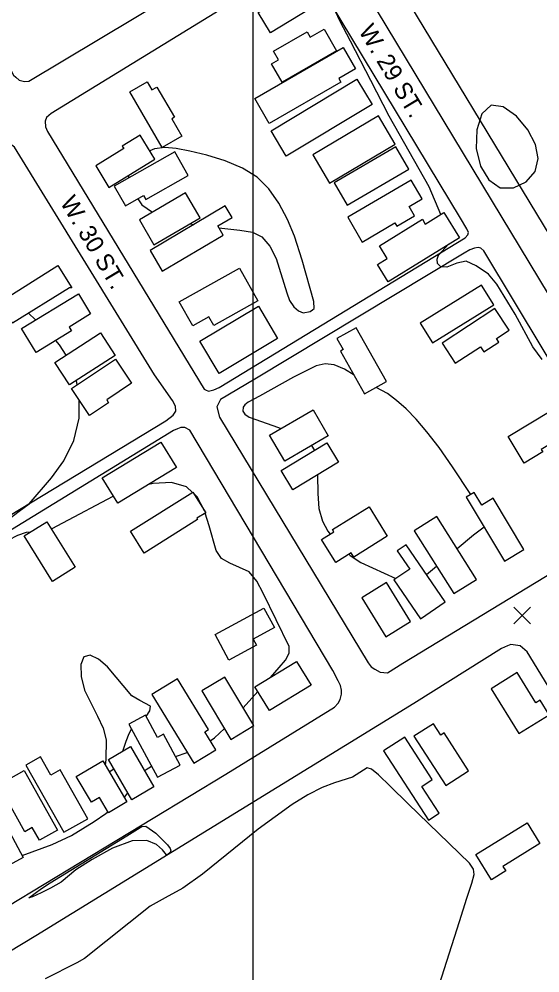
# Model space of a CAD drawing. Extents: x 79600 to 91800, y 75600 to 84400.
# Drawn here: x 82798 to 83248, y 82011 to 82835 of the extents above; entities that cross this region are included whole.
import ezdxf

# ---------------------------------------------------------------- set-up
doc = ezdxf.new("R2010")
doc.units = 0
for name, color, linetype in [('084-085$0$BLDG', 7, 'Continuous'), ('084-085$0$GRID', 7, 'Continuous'), ('084-085$0$INDEX', 7, 'Continuous'), ('084-085$0$INTER', 7, 'Continuous'), ('084-085$0$RECREATION', 7, 'Continuous'), ('084-085$0$ROAD', 7, 'Continuous'), ('084-085$0$ROAD-NAME', 7, 'Continuous'), ('084-085$0$SPOTMARK', 7, 'Continuous'), ('084-085$0$SPOTS', 7, 'Continuous')]:
    doc.layers.add(name, color=color, linetype=linetype)

# ---------------------------------------------------------------- blocks, each defined once
blk = doc.blocks.new('084-085$0$SPOTX')
at = {"layer": '084-085$0$SPOTMARK'}
for p, q in [((-0.37, 0.358), (0.351, -0.358)), ((-0.012, 0), (-0.37, -0.358)), ((-0.012, 0), (0.347, 0.358))]:
    blk.add_line(p, q, dxfattribs=at)

msp = doc.modelspace()

# ---------------------------------------------------------------- linework, layer by layer
at = {"layer": '084-085$0$BLDG'}
for points in [[(83015.3, 82822.83), (83004.54, 82840.42), (83038.07, 82860.94), (83048.83, 82843.35)], [(83016.15, 82796.11), (83022.2, 82799.6), (83017.83, 82807.18), (83046.8, 82823.89), (83049.6, 82819.04), (83061.6, 82825.96), (83072.31, 82807.38), (83025.28, 82780.27)], [(83088.61, 82791.88), (83074.18, 82783.56), (83075.99, 82780.41), (83014.12, 82744.74), (83001.74, 82766.21), (83078.06, 82810.2)], [(82908.66, 82780.58), (82912.7, 82773.56), (82917.14, 82776.11), (82932.15, 82750.04), (82929.94, 82748.76), (82938.65, 82733.63), (82921.54, 82723.78), (82893.77, 82772.01)], [(83103.08, 82760.93), (83028.91, 82716.48), (83015.82, 82738.32), (83089.99, 82782.77)], [(83051.71, 82717.62), (83066.14, 82693.1), (83123.12, 82726.63), (83108.69, 82751.15)], [(82915.32, 82713.82), (82902.59, 82734.5), (82887.19, 82725.03), (82888.52, 82722.88), (82864.18, 82707.9), (82875.58, 82689.37)], [(83081.55, 82673.99), (83134.77, 82705.04), (83123.5, 82724.36), (83070.28, 82693.3)], [(82905.49, 82682.34), (82907.41, 82678.95), (82944.17, 82699.8), (82932.63, 82720.17), (82880.24, 82690.46), (82889.87, 82673.48)], [(83094.58, 82642.23), (83122.83, 82658.74), (83124.51, 82655.87), (83139.74, 82664.78), (83135.04, 82672.83), (83146.46, 82679.5), (83136.96, 82695.76), (83082.05, 82663.65)], [(82941.93, 82684.68), (82901.91, 82661.33), (82914.53, 82639.7), (82954.55, 82663.06)], [(82969.61, 82656.1), (82982.05, 82663.44), (82976.21, 82673.35), (82911.11, 82634.94), (82921.7, 82616.99), (82974.35, 82648.06)], [(83107.86, 82622.75), (83116.21, 82627.89), (83109.32, 82639.08), (83146.48, 82661.95), (83149.03, 82657.8), (83165.13, 82667.71), (83178.59, 82645.85), (83116.98, 82607.92)], [(82843.49, 82602.81), (82841.44, 82602.8), (82792.23, 82572.07), (82780.89, 82590.24), (82831.58, 82621.89)], [(82966.34, 82570.01), (82962.01, 82577.68), (82948.12, 82569.82), (82936.45, 82590.44), (82988.34, 82619.79), (83004.34, 82591.51)], [(83155.38, 82555.04), (83208.17, 82587.86), (83197.48, 82605.04), (83144.7, 82572.22)], [(82859.81, 82580.08), (82841.26, 82568.79), (82843.28, 82565.46), (82812.72, 82546.86), (82800.07, 82567.65), (82849.18, 82597.54)], [(83004.74, 82586.78), (83021.36, 82558.92), (82970.83, 82528.78), (82954.21, 82556.64)], [(83174.95, 82537.6), (83196.66, 82551.82), (83199.55, 82547.41), (83212.47, 82555.88), (83210.47, 82558.94), (83221.47, 82566.15), (83209.25, 82584.79), (83163.62, 82554.89)], [(83072.61, 82558.81), (83078.03, 82549.3), (83075.63, 82547.93), (83096.61, 82511.05), (83115.6, 82521.85), (83089.21, 82568.25)], [(82880.91, 82544.2), (82841.56, 82518.75), (82828.92, 82538.28), (82868.28, 82563.73)], [(82873.77, 82505.89), (82875.38, 82503.47), (82858.74, 82492.35), (82843.21, 82515.6), (82881.29, 82541.04), (82895.2, 82520.21)], [(83014.52, 82475.42), (83052.09, 82497.23), (83065.1, 82474.82), (83027.53, 82453.02)], [(83249.29, 82463.13), (83250.55, 82461.08), (83234.61, 82451.33), (83220.66, 82474.13), (83258.29, 82497.15), (83270.99, 82476.4)], [(82869.87, 82438.45), (82920.57, 82469.31), (82933.87, 82447.47), (82883.17, 82416.61)], [(83024.47, 82444.91), (83063.99, 82468.78), (83074.14, 82451.97), (83034.62, 82428.1)], [(82951.63, 82403.66), (82952.3, 82402.59), (82906.15, 82373.63), (82894.31, 82392.5), (82948.1, 82426.25), (82959.27, 82408.45)], [(83197.9, 82414.94), (83191.32, 82425.93), (83184.46, 82421.82), (83217.53, 82366.64), (83234.29, 82376.69), (83207.8, 82420.87)], [(83085, 82373.66), (83071.79, 82365.44), (83059.42, 82385.31), (83070.12, 82391.97), (83068.97, 82393.81), (83100.41, 82413.38), (83116.11, 82388.15), (83087.19, 82370.14)], [(82826.75, 82349.1), (82802.39, 82388.33), (82821.98, 82400.5), (82846.35, 82361.27)], [(83139.44, 82392.93), (83173.76, 82338.53), (83193.34, 82350.88), (83159.02, 82405.28)], [(83124.82, 82375.56), (83135.61, 82359.79), (83121.9, 82350.41), (83144.89, 82316.8), (83166.23, 82331.4), (83132.45, 82380.78)], [(83094.05, 82334.82), (83114.8, 82301.35), (83136.17, 82314.59), (83115.43, 82348.07)], [(83018.67, 82309.21), (83000.37, 82299.3), (83003.25, 82294), (82979.33, 82281.04), (82967.3, 82303.25), (83009.51, 82326.11)], [(83050.36, 82259.45), (83014.32, 82237.58), (83001.83, 82258.16), (83037.86, 82280.03)], [(83256.03, 82233.98), (83248.35, 82246.4), (83244.7, 82244.15), (83228.52, 82270.31), (83206.02, 82256.4), (83229.88, 82217.81)], [(82967.98, 82203.58), (82958.49, 82219.08), (82961.78, 82221.09), (82934.92, 82265), (82912.67, 82251.38), (82949.01, 82191.98)], [(83000.85, 82224.59), (82975.73, 82266.46), (82955.9, 82254.57), (82981.01, 82212.69)], [(82922.73, 82217.22), (82917.5, 82214.39), (82907.17, 82233.46), (82892.9, 82225.73), (82917.72, 82179.9), (82937.22, 82190.46)], [(83186.45, 82185.64), (83165.44, 82218.28), (83162.39, 82216.32), (83156.01, 82226.22), (83139.27, 82215.44), (83166.67, 82172.9)], [(83161.03, 82148.85), (83146.02, 82172.01), (83155.1, 82177.89), (83131.26, 82214.66), (83112.9, 82202.76), (83151.75, 82142.83)], [(82895.37, 82160.58), (82875.13, 82195.34), (82894.31, 82206.5), (82914.55, 82171.75)], [(82825.44, 82181.72), (82816.42, 82197.65), (82803.87, 82190.54), (82836.77, 82132.41), (82857.32, 82144.04), (82833.43, 82186.24)], [(82875.11, 82149.26), (82867.4, 82162.44), (82860.46, 82158.38), (82847.41, 82180.7), (82870.31, 82194.09), (82891.07, 82158.6)], [(82815.55, 82125.55), (82809.38, 82136.53), (82803, 82132.94), (82780.28, 82173.33), (82802.3, 82185.72), (82831.19, 82134.35)], [(82789.44, 82104.17), (82790.73, 82104.17), (82790.23, 82103.9), (82787.68, 82108.59), (82780.37, 82104.61), (82759.19, 82143.54), (82778.05, 82153.8), (82801.48, 82110.72)], [(83216.13, 82102.96), (83218.6, 82099), (83206.35, 82091.38), (83192.77, 82113.21), (83236.96, 82140.7), (83248.08, 82122.83)]]:
    msp.add_lwpolyline(points, close=True, dxfattribs=at)
at = {"layer": '084-085$0$GRID'}
msp.add_line((83000, 84000), (83000, 80000), dxfattribs=at)
at = {"layer": '084-085$0$INDEX'}
for points in [[(83162.6, 82666.15), (83152.51, 82689.84), (83117.84, 82750.87), (83101.85, 82781.84), (83084.37, 82815.78), (83075.04, 82833.28), (83067.83, 82848.78)], [(83250.06, 82540.81), (83242, 82551.82), (83226.63, 82579.9), (83210.86, 82605.93), (83203.57, 82614.58), (83193.04, 82621.81), (83184.49, 82625.76), (83176.27, 82623.95), (83167.71, 82620.66), (83162.45, 82620.83), (83159.49, 82623.62), (83159.16, 82627.4), (83160.31, 82630.86), (83169.03, 82640.39)]]:
    msp.add_lwpolyline(points, dxfattribs=at)
for points in [[(83237.75, 82739.25), (83227.82, 82751.02), (83216.47, 82759.14), (83205.9, 82760.43), (83198.04, 82752.88), (83193.64, 82739.12), (83193.13, 82722.9), (83196.77, 82707.72), (83203.93, 82695.81), (83213.8, 82689.11), (83225.27, 82688.94), (83236.12, 82694.2), (83243.87, 82703.18), (83246.55, 82714.3), (83244.3, 82726.6)], [(82824.81, 82088.73), (82891.07, 82129.32), (82902.57, 82136.44), (82904.07, 82137.43), (82907.5, 82137.61), (82916.29, 82131.61), (82926.25, 82121.63), (82928.5, 82118.41), (82929.02, 82116.54), (82928.14, 82114.73), (82926.72, 82113.5), (82925.3, 82112.87), (82921.89, 82117.28), (82916.86, 82121.8), (82908.34, 82125.45), (82895.59, 82125.06), (82878.7, 82118.66), (82861.09, 82108.98), (82847.03, 82099.97), (82834.47, 82089.46), (82825.2, 82084.18), (82817.03, 82080.11), (82809.49, 82076.68), (82806.26, 82075.83), (82817.22, 82083.86)]]:
    msp.add_lwpolyline(points, close=True, dxfattribs=at)
at = {"layer": '084-085$0$INTER'}
for p, q in [((82892.18, 82699.58), (82892.9, 82697.64)), ((82945.72, 82657.91), (82948.94, 82657.26)), ((82812.15, 82575), (82806.08, 82580.72)), ((82848.3, 82519), (82847.65, 82522.69)), ((83050.65, 82466.44), (83053.23, 82462.28)), ((83150.1, 82354.98), (83158.76, 82362.31)), ((82991.65, 82239.92), (83004.3, 82254.09)), ((82933.25, 82197.79), (82943.34, 82201.25)), ((82875.85, 82184.63), (82879.79, 82187.35))]:
    msp.add_line(p, q, dxfattribs=at)
for points in [[(83051.57, 82583.61), (83052.97, 82584.84), (83052.76, 82590.92), (83042.54, 82626.61), (83035.88, 82647.28), (83029.89, 82661.66), (83022.51, 82675.9), (83013.93, 82688.12), (83003.68, 82698.12), (82991.14, 82706.15), (82976.14, 82712.45), (82960.29, 82717.24), (82945.63, 82720.73), (82933.68, 82723.04), (82923.86, 82723.83), (82915.01, 82722.65), (82910.86, 82721.05)], [(82900.47, 82679.49), (82904.01, 82674.3), (82913.17, 82667.9)], [(82970.57, 82654.48), (82988.79, 82652.53), (82999.61, 82650.89), (83007.78, 82646.72), (83014.58, 82638.62), (83020.15, 82627.96), (83029.28, 82598.43), (83031.8, 82591.61), (83035.34, 82586.4), (83039.48, 82582.89), (83043.52, 82581.15), (83049.55, 82582.23), (83051.57, 82583.61)], [(82838.78, 82544.65), (82832.89, 82553.58), (82829.66, 82557.17)], [(83087.45, 82527.14), (83079.09, 82532.29), (83070.39, 82536.22), (83062.51, 82537.16), (83054.71, 82535.27), (83035.16, 82525.4), (83005.67, 82509.23), (82995.88, 82503.81), (82993.2, 82501.65), (82991.68, 82499.63), (82991.47, 82496.07), (82993.21, 82493.58), (82996.76, 82491.01), (83017.15, 82483.7), (83024.48, 82481.2)], [(83188.4, 82424.17), (83172.68, 82448.01), (83160.89, 82464.65), (83150.46, 82478.36), (83141.24, 82489.25), (83132.61, 82498.07), (83124.19, 82505.44), (83116.41, 82511.27), (83106.51, 82516.69)], [(82750.96, 82362.41), (82748.65, 82361.81), (82741.75, 82361.86), (82743.31, 82366.31), (82763.72, 82383.73), (82797.97, 82409.65), (82806.57, 82416.18), (82825.99, 82438.65), (82836.56, 82453.38), (82845.36, 82470.94), (82849.81, 82490.05), (82850.02, 82505.41)], [(82947.75, 82426.03), (82942.67, 82430.78), (82929.68, 82434.47), (82913.91, 82433.61), (82909.08, 82432.38)], [(83055.86, 82440.93), (83056.05, 82425.14), (83057.07, 82411.94), (83060.12, 82401.13), (83064.86, 82392.38), (83066.88, 82389.95)], [(82958.22, 82410.12), (82952, 82422.06), (82948.93, 82424.93)], [(82879.51, 82422.62), (82878.98, 82422.41), (82835.45, 82399.47), (82826.23, 82394.39), (82825.87, 82394.24)], [(83015.16, 82266.25), (83022.85, 82274.86), (83028.3, 82281.05), (83031.5, 82287.07), (83031.47, 82292.88), (83008.89, 82338.99), (83003.52, 82349.23), (82996.8, 82357.27), (82980.06, 82364.86), (82972.93, 82368.79), (82968.29, 82375.67), (82962.32, 82397.14), (82958.84, 82408.18)], [(83176.61, 82377.41), (83190.6, 82389.25), (83199.87, 82396.11)], [(82807.87, 82391.74), (82803.95, 82391.49), (82796.56, 82388.86), (82788.82, 82384.65), (82779.43, 82376.23), (82776.51, 82372.69), (82770.67, 82368.93), (82768.33, 82368.02)], [(83083.12, 82372.49), (83084.11, 82371.62), (83093.45, 82365.5), (83123.47, 82351.49)], [(82907.77, 82232.34), (82910.9, 82237.19), (82911.56, 82241.3), (82902.41, 82246.12), (82895.3, 82250.22), (82874.34, 82275.29), (82866.67, 82282.08), (82859.48, 82285.44), (82854.03, 82284.09), (82851.34, 82277.35), (82851.52, 82266.91), (82854.45, 82255.05), (82865.76, 82232.81), (82870.7, 82222.41), (82873.13, 82212.33), (82872.98, 82195.18), (82872.44, 82190.46)], [(82887.51, 82202.54), (82890.48, 82211.08), (82893.13, 82217.64), (82895.23, 82221.43)], [(82963.13, 82211.49), (82966.78, 82214.01), (82975.39, 82222.06)], [(83156.74, 81986.87), (83178.47, 82055.42), (83184.98, 82075.62), (83189.36, 82088.51), (83191.29, 82095.85), (83190.67, 82100.63), (83187.22, 82105.64), (83134.23, 82157), (83118.7, 82172.2), (83108.5, 82182.1), (83102.55, 82187), (83098.77, 82188.05), (83086.1, 82180.16), (83070.43, 82175.04), (83059.87, 82171.07), (83047.59, 82164.78), (83033.97, 82156.37), (83004.68, 82135.21), (82956.6, 82096.15), (82939.44, 82084.11), (82924.33, 82075.87), (82911.2, 82068.66), (82854.51, 82023.51), (82847.84, 82019.79), (82820.6, 82005.93)], [(82906.51, 82185.54), (82907.87, 82186.74), (82912.51, 82189.52)], [(82888.82, 82162.45), (82889.29, 82162.91), (82891.87, 82166.6)], [(82800.51, 82112.49), (82826.5, 82121.77), (82843.25, 82129.63), (82862.87, 82141.86), (82872.79, 82148.72), (82874.6, 82150.13)]]:
    msp.add_lwpolyline(points, dxfattribs=at)
at = {"layer": '084-085$0$RECREATION'}
msp.add_lwpolyline([(83263.53, 82636.72), (83111.76, 82887.32), (83287.39, 82994.15), (83433.35, 82754.08), (83376.35, 82718.43)], dxfattribs=at)
at = {"layer": '084-085$0$ROAD'}
for points in [[(82508.5, 83257.27), (82791, 82789.98), (82793.2, 82786.42), (82795.08, 82784.57), (82797.89, 82782.1), (82802.72, 82780.89), (82806.45, 82781.06), (83019.27, 82908.66)], [(83090.72, 82869.46), (83354.53, 82432.68), (83357.19, 82429.59), (83364.83, 82425.91), (83369.81, 82426.09), (83373.37, 82427.52), (83581.54, 82552.75), (83584.32, 82555.56), (83585.86, 82558.53), (83586.13, 82564.44), (83584.85, 82569.87), (83575.58, 82585.98), (83306.91, 83030.5)], [(82793.9, 82724.24), (82790.47, 82726.7), (82787.82, 82727.46), (82780.21, 82725.55), (82776.49, 82723.66), (82595.27, 82614.3), (82592.02, 82611.95), (82591.26, 82610.24), (82590.96, 82608.37), (82591.14, 82604.95), (82592.87, 82601.69), (82729.53, 82380.38), (82731.25, 82378.22), (82733.44, 82376.99), (82736.86, 82376.7), (82741.52, 82377.04), (82750.51, 82382.53), (82924.91, 82487.81)], [(82924.91, 82487.81), (82931.1, 82492.66), (82933.41, 82496.26), (82933.22, 82500.45), (82930.55, 82505.26), (82915.02, 82527.39), (82793.9, 82724.24)], [(82725.05, 82030.69), (82976.59, 82182.62), (83070.44, 82240.58), (83073.84, 82243.87), (83075.38, 82247.15), (83076.59, 82251.66), (83076.57, 82255.24), (83075.76, 82259.28), (83073.87, 82263.31), (83069.15, 82272.29), (82945.64, 82479.7), (82941.27, 82482.16), (82937.69, 82482.13), (82934.9, 82481.03), (82931.34, 82479.45), (82536.71, 82237.99)], [(83431.27, 81974.36), (83365, 82079.35), (83236.97, 82288.28), (83233.06, 82291.83), (83231.03, 82293.37), (83223.09, 82294.57), (83219.99, 82293.46), (83215.03, 82291.1), (83138.99, 82243.66), (82812.35, 82042.9), (82548.12, 81883.42)]]:
    msp.add_lwpolyline(points, dxfattribs=at)
for points in [[(83067.22, 82848.94), (83052.13, 82875.59), (83049.46, 82879.31), (83046.96, 82881.62), (83044.93, 82882.39), (83042.75, 82882.68), (83039.33, 82882.51), (83035.45, 82881.55), (83031.89, 82879.82), (82825.59, 82753.2), (82821.73, 82749.91), (82820.5, 82746.48), (82820.84, 82741.82), (82822.58, 82737.63), (82957.85, 82515.22), (82958.94, 82514.45), (82961.75, 82513.54), (82966.41, 82514.65), (82970.75, 82516.55), (83183.4, 82645.85), (83185.87, 82648.35), (83186.33, 82650.38), (83185.06, 82653.63), (83179.56, 82662.77)], [(83001.8, 82523.74), (82972.06, 82506.14), (82968.83, 82499.9), (82971.22, 82491.05), (83099.74, 82278.86), (83102.25, 82275.46), (83105.37, 82273.3), (83109.9, 82270.84), (83116.27, 82270.26), (83129.59, 82278.43), (83329.24, 82399.56), (83331.86, 82403), (83330.37, 82417.14), (83199.64, 82634.76), (83196.98, 82636.92), (83194.8, 82637.53), (83191.7, 82637.04), (83187.51, 82635.46), (83182.55, 82632.63)]]:
    msp.add_lwpolyline(points, close=True, dxfattribs=at)

# ---------------------------------------------------------------- block references
at = {"layer": '084-085$0$SPOTS', "xscale": 20, "yscale": 20}
msp.add_blockref('084-085$0$SPOTX', (83233, 82319.69), dxfattribs=at)

# ---------------------------------------------------------------- texts
at = {"layer": '084-085$0$ROAD-NAME'}
for s, p in [('W. 29 ST.', (83090.94, 82824.63)), ('W. 30 ST.', (82832.96, 82676.53))]:
    msp.add_text(s, height=15, rotation=300.88308, dxfattribs=at).set_placement(p)

doc.saveas('drawing.dxf')
